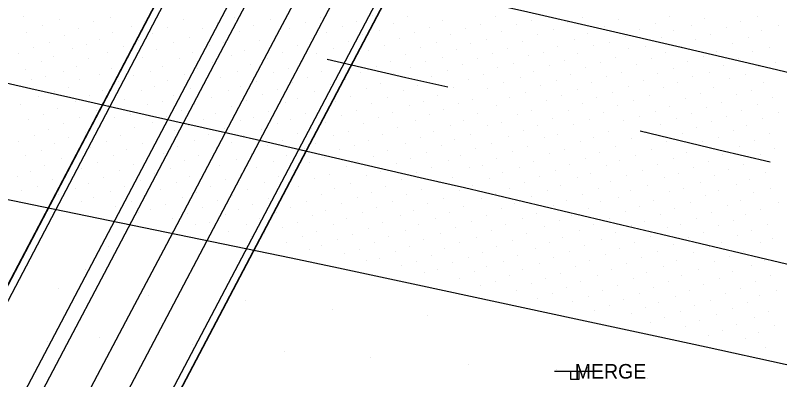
# Model space of a CAD drawing. Extents: x 1732346 to 1733076, y 467730 to 468633.
# Drawn here: x 1732679.1 to 1732773.5, y 467993.7 to 468038.7 of the extents above; entities that cross this region are included whole.
import ezdxf

# ---------------------------------------------------------------- set-up
doc = ezdxf.new("R2010")
doc.units = 0
for name, color, linetype in [('Default', 7, 'Continuous'), ('S_Bridge_BoxCulvert', 7, 'Continuous'), ('S_Ground_SpotElevation', 7, 'Continuous'), ('S_Railroad_Tracks', 7, 'Continuous'), ('S_Roadway_Edge_Pavement', 7, 'Continuous'), ('S_Roadway_Painted_Lines', 7, 'Continuous'), ('S_Text', 7, 'Continuous'), ('S_Traffic_Sign_SinglePost', 7, 'Continuous'), ('TopoDOT Temp', 7, 'Continuous')]:
    doc.layers.add(name, color=color, linetype=linetype)

# ---------------------------------------------------------------- blocks, each defined once
blk = doc.blocks.new('POINT_DISPLAY')
at = {"layer": 'Default'}
blk.add_line((0, 0), (0, 0), dxfattribs=at)

msp = doc.modelspace()

# ---------------------------------------------------------------- linework, layer by layer
at = {"layer": 'S_Bridge_BoxCulvert'}
for p, q in [((1732639.349, 467931.595), (1732772.729, 468185.159)), ((1732639.356, 467931.621), (1732772.736, 468185.185)), ((1732640.157, 467931.201), (1732773.537, 468184.766)), ((1732646.436, 467927.898), (1732779.815, 468181.463)), ((1732656.397, 467922.658), (1732789.777, 468176.223)), ((1732660.637, 467920.428), (1732794.017, 468173.993)), ((1732661.386, 467920.002), (1732794.766, 468173.567)), ((1732661.436, 467920.006), (1732794.816, 468173.571))]:
    msp.add_line(p, q, dxfattribs=at)
at = {"layer": 'S_Railroad_Tracks'}
for points in [[(1732794.809, 468194.505), (1732790.156, 468185.654), (1732786.365, 468178.442), (1732781.701, 468169.596), (1732777.038, 468160.75), (1732772.374, 468151.904), (1732767.711, 468143.058), (1732763.047, 468134.212), (1732758.384, 468125.366), (1732753.721, 468116.52), (1732749.057, 468107.674), (1732744.394, 468098.828), (1732739.73, 468089.982), (1732735.067, 468081.136), (1732730.403, 468072.29), (1732725.74, 468063.444), (1732721.076, 468054.598), (1732716.413, 468045.752), (1732711.749, 468036.906), (1732707.086, 468028.06), (1732702.422, 468019.214), (1732697.759, 468010.368), (1732693.095, 468001.522), (1732688.432, 467992.676)], [(1732680.786, 467989.136), (1732685.443, 467997.986), (1732690.1, 468006.835), (1732694.757, 468015.685), (1732699.414, 468024.534), (1732704.07, 468033.384), (1732708.727, 468042.233), (1732713.384, 468051.083), (1732718.041, 468059.932), (1732722.698, 468068.782), (1732727.355, 468077.631), (1732732.012, 468086.481), (1732736.669, 468095.33), (1732741.325, 468104.18), (1732745.982, 468113.029), (1732750.639, 468121.879), (1732755.296, 468130.728), (1732759.953, 468139.578), (1732764.61, 468148.427), (1732769.267, 468157.277), (1732773.924, 468166.126), (1732778.581, 468174.976), (1732783.237, 468183.825), (1732787.789, 468192.475)]]:
    msp.add_lwpolyline(points, dxfattribs=at)
at = {"layer": 'S_Roadway_Edge_Pavement'}
msp.add_lwpolyline([(1732783.999, 467993.429), (1732774.226, 467995.551), (1732764.454, 467997.672), (1732758.142, 467999.043), (1732748.365, 468001.14), (1732738.587, 468003.236), (1732728.809, 468005.333), (1732719.031, 468007.43), (1732713.162, 468008.689), (1732703.366, 468010.702), (1732693.571, 468012.715), (1732683.776, 468014.728), (1732673.981, 468016.742), (1732664.185, 468018.755), (1732654.309, 468020.785), (1732644.526, 468022.853), (1732634.742, 468024.922), (1732624.958, 468026.99), (1732615.174, 468029.059), (1732605.391, 468031.128), (1732595.607, 468033.196)], dxfattribs=at)
at = {"layer": 'S_Roadway_Painted_Lines'}
for points in [[(1732673.625, 468055.137), (1732683.345, 468052.876), (1732693.157, 468050.571), (1732702.921, 468048.283), (1732712.603, 468046.006), (1732722.336, 468043.724), (1732732.052, 468041.47), (1732741.866, 468039.226), (1732751.581, 468036.995), (1732761.355, 468034.736), (1732771.043, 468032.478), (1732780.799, 468030.178), (1732790.555, 468027.892), (1732800.282, 468025.592), (1732810.076, 468023.293), (1732819.824, 468020.953), (1732829.566, 468018.598)], [(1732717.622, 468033.252), (1732727.359, 468030.982), (1732732.534, 468029.844)], [(1732671.267, 468031.879), (1732681.016, 468029.657), (1732685.939, 468028.534), (1732695.689, 468026.318), (1732705.44, 468024.102), (1732710.153, 468023.031), (1732719.894, 468020.782), (1732729.635, 468018.533), (1732734.577, 468017.392), (1732744.308, 468015.094), (1732754.038, 468012.797), (1732758.93, 468011.642), (1732768.659, 468009.337), (1732778.388, 468007.031), (1732783.256, 468005.878), (1732792.992, 468003.598), (1732802.727, 468001.319), (1732807.74, 468000.145), (1732817.478, 467997.872), (1732827.215, 467995.599)], [(1732756.317, 468024.417), (1732766.037, 468022.076), (1732772.364, 468020.592)]]:
    msp.add_lwpolyline(points, dxfattribs=at)
at = {"layer": 'S_Traffic_Sign_SinglePost'}
msp.add_line((1732745.732, 467994.694), (1732750.722, 467994.694), dxfattribs=at)
msp.add_lwpolyline([(1732747.728, 467994.694), (1732748.726, 467994.694), (1732748.726, 467993.696), (1732747.728, 467993.696)], close=True, dxfattribs=at)
at = {"layer": 'TopoDOT Temp'}
for p, q in [((1732711.749, 468036.906), (1732711.749, 468036.906)), ((1732704.07, 468033.384), (1732704.07, 468033.384)), ((1732707.086, 468028.06), (1732707.086, 468028.06)), ((1732699.414, 468024.534), (1732699.414, 468024.534)), ((1732702.422, 468019.214), (1732702.422, 468019.214)), ((1732694.757, 468015.685), (1732694.757, 468015.685)), ((1732697.759, 468010.368), (1732697.759, 468010.368)), ((1732687.761, 468007.263), (1732687.761, 468007.263)), ((1732690.1, 468006.835), (1732690.1, 468006.835)), ((1732693.095, 468001.522), (1732693.095, 468001.522)), ((1732683.108, 467998.412), (1732683.108, 467998.412)), ((1732685.443, 467997.986), (1732685.443, 467997.986))]:
    msp.add_line(p, q, dxfattribs=at)

# ---------------------------------------------------------------- block references
at = {"layer": 'S_Ground_SpotElevation'}
for p in [(1732723.178, 468038.615), (1732680.04, 468038.551), (1732684.577, 468038.213), (1732688.779, 468037.896), (1732690.883, 468038.371), (1732695.025, 468037.958), (1732699.812, 468038.118), (1732704.097, 468037.806), (1732706.191, 468038.414), (1732710.585, 468038.148), (1732714.947, 468037.786), (1732716.849, 468038.472), (1732721.2, 468037.865), (1732725.845, 468037.694), (1732727.597, 468038.515), (1732731.888, 468038.063), (1732738.414, 468038.486), (1732742.931, 468038.019), (1732747.349, 468037.799), (1732749.158, 468038.404), (1732753.617, 468038.138), (1732758.196, 468037.709), (1732759.96, 468038.484), (1732764.284, 468038.229), (1732768.698, 468037.934), (1732770.78, 468038.504), (1732682.457, 468037.445), (1732686.843, 468037.036), (1732693.402, 468037.309), (1732697.903, 468037.212), (1732702.196, 468037.086), (1732708.529, 468037.459), (1732712.93, 468037.021), (1732719.529, 468037.355), (1732724.048, 468036.832), (1732730.311, 468037.186), (1732734.67, 468037.111), (1732736.594, 468037.56), (1732740.983, 468037.49), (1732745.557, 468036.944), (1732751.883, 468037.308), (1732756.221, 468036.933), (1732760.417, 468036.786), (1732762.597, 468037.422), (1732767.012, 468037.128), (1732771.347, 468036.776), (1732773.428, 468037.372), (1732680.458, 468036.567), (1732685.134, 468036.165), (1732691.144, 468036.581), (1732696.098, 468036.376), (1732700.592, 468035.96), (1732706.785, 468036.675), (1732711.372, 468036.138), (1732715.719, 468035.768), (1732717.491, 468036.596), (1732722.041, 468036.347), (1732726.507, 468035.829), (1732728.455, 468036.527), (1732732.905, 468036.269), (1732739.194, 468036.624), (1732743.639, 468036.294), (1732749.838, 468036.483), (1732754.497, 468036.107), (1732758.938, 468035.89), (1732764.979, 468036.285), (1732769.642, 468035.935), (1732683.364, 468035.345), (1732687.922, 468035.05), (1732689.471, 468035.752), (1732694.294, 468035.547), (1732698.665, 468035.332), (1732703.124, 468034.915), (1732704.84, 468035.377), (1732709.22, 468035.577), (1732713.967, 468034.968), (1732720.209, 468035.48), (1732724.766, 468034.915), (1732731.103, 468035.371), (1732735.278, 468035.223), (1732737.368, 468035.696), (1732741.753, 468035.474), (1732746.078, 468034.838), (1732748.161, 468035.681), (1732750.533, 468034.907), (1732752.521, 468035.342), (1732761.444, 468034.873), (1732763.138, 468035.684), (1732767.69, 468035.177), (1732679.525, 468033.988), (1732681.398, 468034.722), (1732686.15, 468034.581), (1732690.533, 468034.071), (1732692.411, 468034.812), (1732696.597, 468034.5), (1732700.994, 468034.081), (1732707.417, 468034.294), (1732712.07, 468034.076), (1732716.28, 468034), (1732718.457, 468034.64), (1732722.768, 468034.334), (1732729.15, 468034.673), (1732733.561, 468034.415), (1732738.096, 468033.955), (1732739.954, 468034.554), (1732744.401, 468034.049), (1732748.595, 468034.011), (1732754.911, 468034.54), (1732756.976, 468034.813), (1732759.471, 468034.141), (1732765.78, 468034.176), (1732770.162, 468034.166), (1732772.263, 468034.729), (1732682.329, 468033.01), (1732683.839, 468033.554), (1732688.189, 468033.361), (1732692.828, 468033.08), (1732694.777, 468033.501), (1732699.421, 468033.387), (1732705.783, 468033.655), (1732710.214, 468033.392), (1732714.553, 468032.992), (1732721.003, 468033.486), (1732725.47, 468033.013), (1732727.256, 468033.87), (1732729.762, 468032.99), (1732731.828, 468033.509), (1732736.151, 468033.362), (1732742.522, 468033.688), (1732746.945, 468033.114), (1732753.27, 468033.509), (1732757.733, 468033.305), (1732762.201, 468033.037), (1732764.08, 468033.548), (1732768.461, 468033.353), (1732680.387, 468032.001), (1732686.605, 468032.412), (1732690.991, 468032.075), (1732697.286, 468032.394), (1732701.585, 468032.129), (1732703.484, 468032.803), (1732708.184, 468032.553), (1732712.821, 468032.153), (1732719.152, 468032.919), (1732723.686, 468032.362), (1732727.936, 468032.255), (1732734.371, 468032.557), (1732738.717, 468032.267), (1732740.664, 468032.711), (1732745.144, 468032.53), (1732749.592, 468032.259), (1732751.406, 468032.858), (1732755.835, 468032.632), (1732760.365, 468032.098), (1732766.615, 468032.519), (1732770.902, 468032.308), (1732773.041, 468032.905), (1732682.771, 468031.172), (1732685.013, 468031.791), (1732689.461, 468031.393), (1732693.741, 468031.203), (1732695.747, 468031.72), (1732699.944, 468031.389), (1732706.523, 468031.766), (1732710.966, 468031.569), (1732716.898, 468031.68), (1732721.785, 468031.576), (1732725.881, 468031.461), (1732730.541, 468031.076), (1732732.452, 468031.844), (1732736.895, 468031.32), (1732743.17, 468031.767), (1732747.745, 468031.314), (1732752.197, 468031.089), (1732753.973, 468031.662), (1732758.501, 468031.452), (1732762.819, 468031.061), (1732764.895, 468031.604), (1732769.37, 468031.355), (1732681.148, 468030.729), (1732687.052, 468030.777), (1732691.864, 468030.502), (1732697.939, 468030.672), (1732702.511, 468030.206), (1732704.445, 468030.992), (1732708.867, 468030.524), (1732713.294, 468030.386), (1732715.251, 468031.023), (1732718.025, 468030.141), (1732719.913, 468030.735), (1732724.172, 468030.304), (1732735.108, 468030.701), (1732739.356, 468030.35), (1732741.513, 468030.955), (1732745.905, 468030.576), (1732750.317, 468030.411), (1732756.705, 468030.585), (1732760.907, 468030.375), (1732767.331, 468030.861), (1732771.603, 468030.417), (1732683.891, 468029.253), (1732685.619, 468029.783), (1732689.81, 468029.422), (1732694.721, 468029.358), (1732696.279, 468029.868), (1732700.691, 468029.598), (1732705.411, 468029.374), (1732706.976, 468029.942), (1732711.549, 468029.533), (1732716.085, 468029.266), (1732722.504, 468029.628), (1732727.04, 468029.394), (1732728.789, 468029.949), (1732733.283, 468029.798), (1732737.455, 468029.632), (1732742.11, 468029.191), (1732743.978, 468029.981), (1732748.542, 468029.528), (1732752.875, 468029.203), (1732754.81, 468029.856), (1732759.136, 468029.717), (1732765.358, 468029.794), (1732770.035, 468029.42), (1732681.898, 468028.648), (1732688.314, 468028.802), (1732692.574, 468028.29), (1732698.648, 468028.764), (1732703.361, 468028.505), (1732709.63, 468028.871), (1732713.999, 468028.435), (1732720.509, 468028.711), (1732725.091, 468028.568), (1732731.241, 468028.725), (1732735.594, 468028.333), (1732740.176, 468028.513), (1732746.565, 468028.741), (1732750.93, 468028.574), (1732757.44, 468028.713), (1732761.874, 468028.42), (1732763.732, 468029.062), (1732768.233, 468028.843), (1732772.629, 468028.569), (1732679.751, 468027.614), (1732686.491, 468028.024), (1732690.635, 468027.551), (1732695.364, 468027.639), (1732697.236, 468028.007), (1732701.172, 468027.699), (1732705.777, 468027.426), (1732707.697, 468028.196), (1732712.464, 468027.889), (1732716.962, 468027.378), (1732718.64, 468028.062), (1732723.07, 468027.816), (1732727.756, 468027.536), (1732729.53, 468028.087), (1732733.863, 468027.724), (1732738.528, 468027.553), (1732744.76, 468028.151), (1732749.165, 468027.83), (1732753.472, 468027.519), (1732755.536, 468028.184), (1732759.948, 468027.4), (1732764.528, 468027.267), (1732766.399, 468027.905), (1732770.863, 468027.638), (1732682.603, 468026.437), (1732684.297, 468027.173), (1732689.081, 468026.941), (1732693.345, 468026.431), (1732699.653, 468026.91), (1732703.888, 468026.511), (1732710.408, 468026.817), (1732714.988, 468026.54), (1732719.448, 468026.324), (1732721.309, 468026.926), (1732725.671, 468026.639), (1732730.297, 468026.454), (1732731.948, 468027.102), (1732736.246, 468026.516), (1732741.113, 468026.469), (1732742.917, 468026.959), (1732747.44, 468026.91), (1732751.784, 468026.728), (1732758.163, 468026.829), (1732762.674, 468026.57), (1732768.869, 468026.871), (1732773.414, 468026.658), (1732680.705, 468025.827), (1732686.989, 468026.099), (1732691.323, 468026.095), (1732696.008, 468025.449), (1732697.764, 468026.238), (1732702.283, 468025.791), (1732706.959, 468025.658), (1732708.583, 468026.115), (1732713.091, 468025.839), (1732717.383, 468025.477), (1732723.982, 468026.114), (1732728.514, 468025.651), (1732734.491, 468025.729), (1732739.109, 468025.436), (1732745.515, 468025.941), (1732750.007, 468025.863), (1732754.239, 468025.666), (1732756.282, 468026.162), (1732760.736, 468025.883), (1732765.156, 468025.62), (1732766.995, 468026.228), (1732771.455, 468025.925), (1732683.216, 468024.597), (1732685.06, 468025.294), (1732689.676, 468024.976), (1732693.873, 468024.813), (1732700.494, 468025.035), (1732704.99, 468024.704), (1732709.532, 468024.523), (1732711.433, 468025.255), (1732715.66, 468024.718), (1732722.165, 468025.286), (1732726.343, 468024.799), (1732732.894, 468025.1), (1732737.392, 468025.033), (1732741.862, 468024.438), (1732743.651, 468025.107), (1732748.071, 468025.227), (1732758.786, 468025.173), (1732763.248, 468024.873), (1732767.828, 468024.447), (1732769.425, 468025.128), (1732681.492, 468023.823), (1732685.626, 468023.571), (1732687.732, 468024.221), (1732692.087, 468023.86), (1732696.661, 468023.512), (1732698.781, 468024.4), (1732703.001, 468023.98), (1732707.301, 468023.868), (1732713.997, 468024.052), (1732718.426, 468023.845), (1732720.249, 468024.351), (1732724.478, 468023.923), (1732729.102, 468023.59), (1732730.798, 468024.281), (1732735.367, 468023.977), (1732740.023, 468023.731), (1732744.481, 468023.587), (1732746.144, 468023.942), (1732750.592, 468023.575), (1732752.374, 468024.342), (1732757.073, 468024.358), (1732761.497, 468024.076), (1732766.014, 468023.542), (1732772.253, 468024.123), (1732679.489, 468023.122), (1732683.905, 468022.804), (1732690.305, 468023.064), (1732694.748, 468022.8), (1732701.224, 468023.177), (1732705.84, 468022.978), (1732710.306, 468022.629), (1732712.046, 468023.193), (1732716.154, 468022.892), (1732722.704, 468023.196), (1732727.327, 468022.857), (1732731.761, 468022.649), (1732733.376, 468023.289), (1732737.92, 468022.818), (1732748.905, 468023.111), (1732755.251, 468023.484), (1732759.602, 468023.087), (1732763.95, 468023.032), (1732770.468, 468023.225), (1732682.341, 468022.023), (1732686.696, 468021.619), (1732688.395, 468022.374), (1732692.886, 468022.071), (1732697.378, 468021.646), (1732699.122, 468022.419), (1732703.956, 468022.288), (1732708.216, 468021.662), (1732714.763, 468022.212), (1732719.176, 468022.157), (1732721.05, 468022.536), (1732725.133, 468022.026), (1732729.904, 468021.74), (1732735.908, 468022.234), (1732740.581, 468021.836), (1732742.367, 468022.441), (1732745.125, 468021.608), (1732746.95, 468022.126), (1732751.305, 468021.76), (1732753.276, 468022.511), (1732757.75, 468022.14), (1732762.089, 468021.778), (1732768.623, 468022.483), (1732772.937, 468022.246), (1732680.316, 468021.312), (1732684.818, 468020.992), (1732691.264, 468021.326), (1732695.464, 468021.018), (1732699.965, 468020.78), (1732701.768, 468021.339), (1732706.383, 468020.881), (1732712.642, 468021.324), (1732717.354, 468021.081), (1732723.351, 468021.288), (1732727.871, 468020.931), (1732732.584, 468020.727), (1732734.15, 468021.314), (1732738.579, 468020.958), (1732749.59, 468021.006), (1732753.768, 468020.687), (1732755.686, 468021.4), (1732760.383, 468021.039), (1732766.44, 468021.523), (1732771.165, 468021.48), (1732682.72, 468020.166), (1732687.245, 468019.791), (1732689.241, 468020.516), (1732693.669, 468020.212), (1732698.287, 468019.811), (1732704.339, 468020.171), (1732708.937, 468019.86), (1732710.965, 468020.586), (1732715.49, 468020.439), (1732719.971, 468020.039), (1732721.421, 468020.562), (1732726.191, 468020.324), (1732730.554, 468019.914), (1732735.186, 468019.868), (1732736.822, 468020.177), (1732741.363, 468019.834), (1732743.115, 468020.569), (1732747.549, 468020.246), (1732752.191, 468020.081), (1732758.458, 468020.287), (1732762.852, 468019.868), (1732764.757, 468020.621), (1732769.111, 468020.237), (1732680.974, 468019.384), (1732685.275, 468019.066), (1732691.912, 468019.448), (1732696.34, 468019.19), (1732702.635, 468019.463), (1732706.934, 468019.06), (1732713.443, 468019.445), (1732717.861, 468019.024), (1732722.485, 468018.925), (1732724.214, 468019.414), (1732728.716, 468019.247), (1732739.295, 468019.234), (1732745.85, 468019.519), (1732750.216, 468019.088), (1732754.601, 468018.854), (1732756.574, 468019.519), (1732761.001, 468019.118), (1732765.448, 468018.83), (1732767.247, 468019.667), (1732771.773, 468019.267), (1732679.374, 468018.751), (1732683.639, 468018.385), (1732688.109, 468017.921), (1732690.001, 468018.625), (1732694.51, 468018.289), (1732698.949, 468017.969), (1732700.565, 468018.705), (1732705.089, 468018.353), (1732709.848, 468017.99), (1732711.553, 468018.739), (1732716.086, 468018.511), (1732720.515, 468017.934), (1732726.844, 468018.343), (1732731.353, 468017.975), (1732733.096, 468018.685), (1732737.734, 468018.477), (1732741.991, 468017.988), (1732743.924, 468018.756), (1732748.534, 468018.64), (1732752.596, 468018.167), (1732759.32, 468018.62), (1732763.738, 468018.082), (1732769.776, 468018.407), (1732679.808, 468017.087), (1732681.83, 468017.555), (1732686.483, 468017.272), (1732692.536, 468017.587), (1732697.055, 468017.147), (1732703.245, 468017.534), (1732707.753, 468017.17), (1732714.085, 468017.532), (1732718.555, 468017.228), (1732724.867, 468017.551), (1732729.301, 468017.205), (1732734.016, 468017.015), (1732735.632, 468017.654), (1732740.14, 468017.249), (1732744.854, 468017.025), (1732746.417, 468017.596), (1732751.099, 468017.306), (1732755.151, 468017.061), (1732757.264, 468017.635), (1732759.938, 468016.898), (1732761.653, 468017.297), (1732765.939, 468016.982), (1732768.17, 468017.745), (1732772.468, 468017.29), (1732684.472, 468016.541), (1732688.753, 468016.117), (1732690.819, 468016.863), (1732695.064, 468016.442), (1732699.768, 468016.118), (1732701.48, 468016.785), (1732705.934, 468016.465), (1732710.341, 468016.061), (1732712.326, 468016.818), (1732716.868, 468016.506), (1732721.36, 468016.175), (1732723.128, 468016.847), (1732727.444, 468016.539), (1732731.961, 468016.098), (1732736.702, 468016.032), (1732738.424, 468016.676), (1732742.886, 468016.27), (1732749.171, 468016.519), (1732753.651, 468016.203), (1732764.371, 468016.379), (1732770.296, 468016.755), (1732687.292, 468015.644), (1732691.431, 468015.027), (1732693.394, 468015.712), (1732697.659, 468015.313), (1732704.113, 468015.83), (1732708.458, 468015.309), (1732715.02, 468015.723), (1732719.415, 468015.489), (1732725.672, 468015.722), (1732730.038, 468015.377), (1732734.494, 468015.101), (1732740.772, 468015.438), (1732745.603, 468015.175), (1732747.171, 468015.796), (1732751.448, 468015.659), (1732756.167, 468015.099), (1732757.905, 468015.754), (1732762.549, 468015.524), (1732767.095, 468015.131), (1732768.753, 468015.851), (1732773.36, 468015.503), (1732694.337, 468014.266), (1732695.761, 468014.725), (1732700.427, 468014.19), (1732702.203, 468014.944), (1732706.713, 468014.669), (1732711.367, 468014.295), (1732713.033, 468014.971), (1732717.404, 468014.591), (1732722.031, 468014.29), (1732723.712, 468014.969), (1732728.294, 468014.609), (1732732.725, 468014.294), (1732739.147, 468014.757), (1732743.438, 468014.238), (1732749.911, 468014.754), (1732754.473, 468014.471), (1732758.799, 468014.087), (1732760.6, 468014.868), (1732765.068, 468014.276), (1732769.375, 468014.114), (1732771.228, 468014.653), (1732698.479, 468013.602), (1732703.123, 468013.099), (1732705.065, 468014.013), (1732709.29, 468013.526), (1732713.898, 468013.118), (1732715.812, 468013.956), (1732720.009, 468013.528), (1732724.43, 468013.108), (1732726.636, 468013.985), (1732731.026, 468013.56), (1732735.449, 468013.241), (1732737.275, 468013.892), (1732741.734, 468013.56), (1732746.276, 468013.33), (1732747.824, 468013.979), (1732752.487, 468013.538), (1732756.881, 468013.145), (1732763.301, 468013.592), (1732767.79, 468013.333), (1732701.346, 468012.863), (1732707.613, 468012.844), (1732712.069, 468012.493), (1732718.361, 468012.827), (1732722.699, 468012.39), (1732728.939, 468012.776), (1732733.496, 468012.485), (1732739.602, 468012.79), (1732744.453, 468012.603), (1732750.529, 468012.816), (1732755.198, 468012.751), (1732759.668, 468012.404), (1732761.237, 468012.823), (1732766.02, 468012.69), (1732772.023, 468012.784), (1732705.46, 468012.007), (1732708.255, 468011.317), (1732709.926, 468011.669), (1732714.593, 468011.294), (1732716.337, 468011.96), (1732720.796, 468011.618), (1732725.195, 468011.314), (1732727.302, 468012.12), (1732731.636, 468011.733), (1732736.053, 468011.263), (1732737.949, 468012.095), (1732742.196, 468011.697), (1732746.676, 468011.286), (1732748.824, 468012.129), (1732753.314, 468011.84), (1732757.605, 468011.292), (1732764.073, 468011.849), (1732768.392, 468011.423), (1732770.051, 468012.107), (1732712.614, 468010.591), (1732716.949, 468010.291), (1732718.865, 468010.943), (1732723.503, 468010.615), (1732729.484, 468010.965), (1732734.01, 468010.555), (1732740.584, 468010.916), (1732745.138, 468010.654), (1732751.486, 468011.012), (1732755.596, 468010.6), (1732760.37, 468010.313), (1732762.288, 468011.192), (1732766.308, 468010.619), (1732771.203, 468010.608), (1732772.661, 468011.098), (1732690.603, 468010.156), (1732715.479, 468009.772), (1732721.665, 468009.776), (1732726.123, 468009.451), (1732727.794, 468010.139), (1732732.117, 468009.819), (1732736.779, 468009.412), (1732738.574, 468010.138), (1732743.342, 468009.904), (1732747.6, 468009.445), (1732749.377, 468010.213), (1732753.804, 468009.82), (1732758.396, 468009.498), (1732762.893, 468009.431), (1732764.838, 468010.09), (1732769.128, 468009.519), (1732719.818, 468009.191), (1732722.464, 468008.393), (1732724.039, 468008.679), (1732730.5, 468009.046), (1732735.132, 468008.759), (1732741.177, 468009.05), (1732745.636, 468008.751), (1732752.051, 468009.069), (1732756.528, 468008.715), (1732767.396, 468008.842), (1732771.626, 468008.375), (1732726.836, 468007.726), (1732728.688, 468008.309), (1732733.138, 468008.079), (1732737.342, 468007.626), (1732739.411, 468008.305), (1732743.9, 468008.003), (1732748.29, 468007.637), (1732750.003, 468008.353), (1732754.583, 468008.062), (1732759.2, 468007.693), (1732760.798, 468008.347), (1732765.455, 468008.201), (1732770.03, 468007.722), (1732729.634, 468006.849), (1732731.288, 468007.228), (1732735.837, 468006.97), (1732740.129, 468006.519), (1732741.804, 468007.212), (1732746.491, 468006.83), (1732751.021, 468006.518), (1732752.808, 468007.29), (1732757.145, 468006.93), (1732761.466, 468006.517), (1732763.499, 468007.241), (1732767.743, 468007.051), (1732772.444, 468006.517), (1732733.99, 468006.116), (1732738.418, 468005.797), (1732744.575, 468006.127), (1732748.962, 468005.796), (1732755.448, 468006.182), (1732759.861, 468005.773), (1732766.16, 468006.119), (1732770.529, 468005.769), (1732684.449, 468004.96), (1732736.632, 468005.291), (1732741.018, 468004.636), (1732742.86, 468005.488), (1732747.173, 468005.019), (1732751.646, 468004.628), (1732753.476, 468005.335), (1732757.975, 468005.014), (1732762.413, 468004.652), (1732764.145, 468005.404), (1732768.758, 468004.985), (1732773.196, 468004.636), (1732695.578, 468004.079), (1732743.572, 468003.733), (1732745.418, 468004.272), (1732749.932, 468003.904), (1732756.252, 468004.292), (1732760.672, 468003.904), (1732766.806, 468004.335), (1732771.011, 468004.092), (1732707.517, 468003.388), (1732747.986, 468003.299), (1732752.565, 468002.828), (1732754.203, 468003.51), (1732758.605, 468003.16), (1732763.016, 468002.816), (1732764.987, 468003.495), (1732769.519, 468003.252), (1732718.233, 468002.33), (1732750.663, 468002.186), (1732755.199, 468001.775), (1732757.02, 468002.581), (1732761.281, 468002.055), (1732767.774, 468002.507), (1732772.1, 468002.047), (1732730, 468001.561), (1732759.287, 468001.36), (1732763.646, 468001.011), (1732765.699, 468001.748), (1732770.393, 468001.33), (1732757.629, 468000.702), (1732761.894, 468000.237), (1732768.268, 468000.531), (1732772.862, 468000.32), (1732764.709, 467999.153), (1732766.524, 467999.784), (1732770.983, 467999.454), (1732689.553, 467998.895), (1732701.025, 467997.997), (1732769.31, 467998.779), (1732712.402, 467997.104), (1732771.73, 467997.695), (1732722.972, 467996.452), (1732735.092, 467995.592), (1732745.921, 467994.893), (1732683.265, 467993.859), (1732757.203, 467993.768)]:
    msp.add_blockref('POINT_DISPLAY', p, dxfattribs=at)

# ---------------------------------------------------------------- texts
at = {"layer": 'S_Text'}
msp.add_text('MERGE', height=1.8, dxfattribs=at).set_placement((1732748.227, 467993.794))

doc.saveas('drawing.dxf')
